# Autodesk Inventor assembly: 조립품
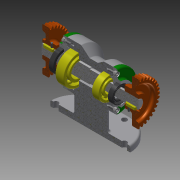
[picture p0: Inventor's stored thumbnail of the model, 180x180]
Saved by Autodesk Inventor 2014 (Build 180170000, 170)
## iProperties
Created: 2020-01
Part Number: 조립품
Document SubType Name: Assembly
Designer: kh
Author: kh
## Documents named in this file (13)
- C:\Users\kh\Desktop\700104V1029\조립품.iam
- C:\Users\kh\Desktop\700104V1029\본체.ipt
- C:\Users\kh\Desktop\700104V1029\축.ipt
- C:\Users\kh\Desktop\700104V1029\베어링 6203.ipt
- C:\Users\kh\Desktop\700104V1029\베어링 6205.ipt
- C:\Users\kh\Desktop\700104V1029\뒤커버.ipt
- C:\Users\kh\Desktop\700104V1029\앞커버.ipt
- C:\Users\kh\Desktop\700104V1029\오일 실 17 30 8.ipt
- C:\Users\kh\Desktop\700104V1029\오일 실 25 38 8.ipt
- C:\Users\kh\Desktop\700104V1029\키 5 x 5 x 18.ipt
- C:\Users\kh\Desktop\700104V1029\스퍼기어.ipt
- C:\Users\kh\Desktop\700104V1029\볼트 M4.ipt
- C:\Users\kh\Desktop\700104V1029\멈춤나사 M3.ipt
